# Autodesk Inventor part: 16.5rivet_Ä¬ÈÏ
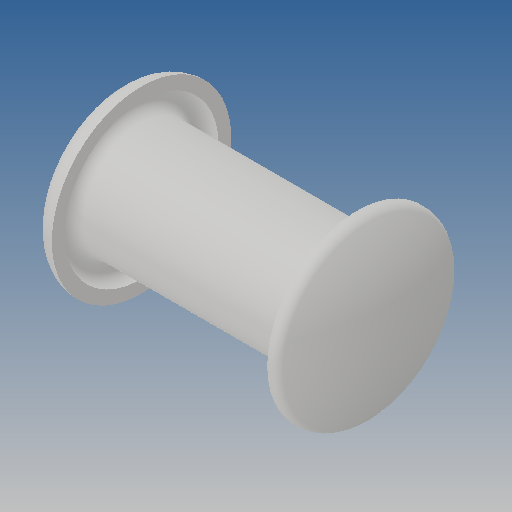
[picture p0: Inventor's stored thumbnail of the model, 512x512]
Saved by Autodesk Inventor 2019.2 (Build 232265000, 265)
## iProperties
Created: 2010-06
Part Number: 16.5rivet_Ä¬ÈÏ
Material: Ogólny
Document SubType Name: Modeling
Designer: CADENGINEERING4
Density: 1 g/cm^3
Appearance: Domyślna
Author: CADENGINEERING4
Revision Number: ÈÎºÎ
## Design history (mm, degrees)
feature "NONE"
node "Bryła1"
